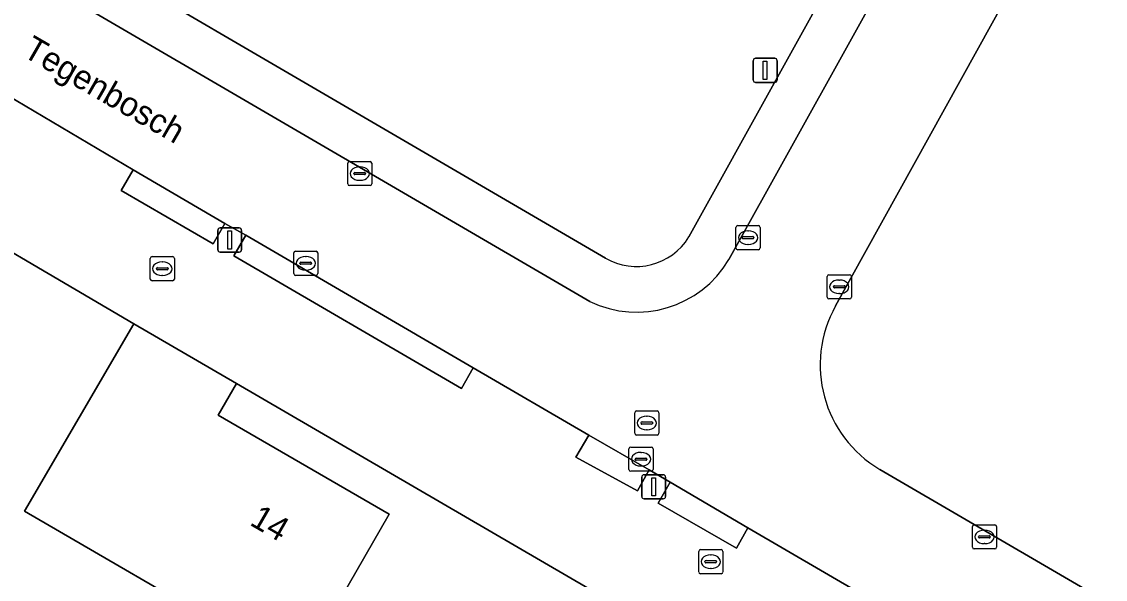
# Model space of a CAD drawing. Extents: x 156502 to 159075, y 384229 to 386100.
# Drawn here: x 157150.95 to 157195.85, y 385818.95 to 385842.02 of the extents above; entities that cross this region are included whole.
import ezdxf

# ---------------------------------------------------------------- set-up
doc = ezdxf.new("R2010")
doc.units = 0
for name, color, linetype in [('IMGEO_Brandkraan', 7, 'Continuous'), ('IMGEO_Erf', 7, 'Continuous'), ('IMGEO_Grasland_overig', 7, 'Continuous'), ('IMGEO_Groenvoorziening', 7, 'Continuous'), ('IMGEO_Haag', 7, 'Continuous'), ('IMGEO_Hek', 7, 'Continuous'), ('IMGEO_Kolk', 7, 'Continuous'), ('IMGEO_Lichtmast', 7, 'Continuous'), ('IMGEO_Openbare_ruimte_label', 7, 'Continuous'), ('IMGEO_Pand', 7, 'Continuous'), ('IMGEO_Pand_nummerreeks', 7, 'Continuous'), ('IMGEO_Parkeervlak_open', 7, 'Continuous'), ('IMGEO_Rijbaan_lokaal_open', 7, 'Continuous'), ('IMGEO_Rioolput', 7, 'Continuous'), ('IMGEO_Voetpad_open', 7, 'Continuous')]:
    doc.layers.add(name, color=color, linetype=linetype)

msp = doc.modelspace()

# ---------------------------------------------------------------- linework, layer by layer
at = {"layer": 'IMGEO_Brandkraan'}
for p, q in [((157156.28, 385831.377), (157156.28, 385832.229)), ((157156.355, 385832.303), (157157.207, 385832.303)), ((157156.768, 385832.083), (157156.793, 385832.083)), ((157157.281, 385832.229), (157157.281, 385831.377)), ((157156.539, 385831.797), (157156.539, 385831.809)), ((157156.977, 385831.76), (157156.579, 385831.76)), ((157156.582, 385831.846), (157156.98, 385831.846)), ((157156.791, 385831.523), (157156.766, 385831.523)), ((157157.023, 385831.809), (157157.023, 385831.797)), ((157157.207, 385831.303), (157156.355, 385831.303))]:
    msp.add_line(p, q, dxfattribs=at)
for points in [[(157156.28, 385831.377), (157156.28, 385832.229)], [(157156.355, 385832.303), (157157.207, 385832.303)], [(157157.281, 385832.229), (157157.281, 385831.377)], [(157157.207, 385831.303), (157156.355, 385831.303)]]:
    msp.add_lwpolyline(points, dxfattribs=at)
for centre, radius, start, end in [((157156.357, 385832.227), 0.0765, 91.552, 178.448), ((157156.357, 385832.227), 0.0765, 91.552, 178.448), ((157157.205, 385832.227), 0.0765, 1.552, 88.448), ((157157.205, 385832.227), 0.0765, 1.552, 88.448), ((157156.579, 385831.806), 0.0403, 85.8775, 175.7526), ((157156.576, 385831.796), 0.0366, 178.938, 274.7102), ((157156.98, 385831.803), 0.043, 264.8664, 352.4533), ((157156.984, 385831.808), 0.0386, 1.7309, 96.639), ((157156.357, 385831.379), 0.0765, 181.552, 268.448), ((157156.357, 385831.379), 0.0765, 181.552, 268.448), ((157157.205, 385831.379), 0.0765, 271.552, 358.448), ((157157.205, 385831.379), 0.0765, 271.552, 358.448)]:
    msp.add_arc(centre, radius, start, end, dxfattribs=at)
for centre, major_axis, ratio, start_param, end_param in [((157156.767, 385831.803), (-0.387, 0.002), 0.722429, 4.712389, 7.853982), ((157156.792, 385831.803), (-0.39, 0.002), 0.717154, 1.570796, 4.712389)]:
    msp.add_ellipse(centre, major_axis=major_axis, ratio=ratio, start_param=start_param, end_param=end_param, dxfattribs=at)
at = {"layer": 'IMGEO_Erf'}
for points in [[(157160.195, 385816.468), (157151.075, 385821.767), (157155.595, 385829.52), (157146.045, 385835.121)], [(157183.031, 385813.57), (157159.85, 385827.054), (157159.093, 385825.747), (157166.175, 385821.643), (157162.465, 385815.184)]]:
    msp.add_lwpolyline(points, dxfattribs=at)
at = {"layer": 'IMGEO_Grasland_overig'}
for points in [[(157198.923, 385855.959), (157184.675, 385830.26)], [(157186.511, 385823.495), (157214.196, 385807.371), (157215.153, 385806.818), (157210.12, 385798.131), (157215.692, 385794.809), (157216.71, 385794.202), (157246.925, 385776.791), (157272.043, 385820.045)]]:
    msp.add_lwpolyline(points, dxfattribs=at)
msp.add_arc((157189.041, 385827.813), 5.005, 150.7337, 239.6346, dxfattribs=at)
at = {"layer": 'IMGEO_Groenvoorziening'}
for points in [[(157120.919, 385863.835), (157175.135, 385832.241)], [(157178.593, 385833.119), (157193.488, 385859.938)]]:
    msp.add_lwpolyline(points, dxfattribs=at)
for points in [[(157159.377, 385833.674), (157155.57, 385835.897), (157155.076, 385835.039), (157158.886, 385832.827)], [(157160.239, 385833.196), (157159.74, 385832.335), (157169.178, 385826.84), (157169.662, 385827.706)], [(157174.449, 385824.915), (157173.918, 385823.999), (157176.468, 385822.604), (157176.957, 385823.481)], [(157177.826, 385822.969), (157177.317, 385822.102), (157180.564, 385820.235), (157181.039, 385821.079)]]:
    msp.add_lwpolyline(points, close=True, dxfattribs=at)
msp.add_arc((157176.416, 385834.444), 2.549, 239.8269, 328.6663, dxfattribs=at)
at = {"layer": 'IMGEO_Haag'}
for points in [[(157159.377, 385833.674), (157155.57, 385835.897), (157155.076, 385835.039), (157158.886, 385832.827)], [(157160.239, 385833.196), (157159.74, 385832.335), (157169.178, 385826.84), (157169.662, 385827.706)], [(157174.449, 385824.915), (157173.918, 385823.999), (157176.468, 385822.604), (157176.957, 385823.481)], [(157177.826, 385822.969), (157177.317, 385822.102), (157180.564, 385820.235), (157181.039, 385821.079)]]:
    msp.add_lwpolyline(points, close=True, dxfattribs=at)
at = {"layer": 'IMGEO_Hek'}
for points in [[(157155.595, 385829.52), (157146.045, 385835.121)], [(157183.031, 385813.57), (157159.85, 385827.054)]]:
    msp.add_lwpolyline(points, dxfattribs=at)
at = {"layer": 'IMGEO_Kolk'}
for p, q in [((157164.46, 385835.314), (157164.46, 385836.166)), ((157164.535, 385836.24), (157165.387, 385836.24)), ((157164.948, 385836.02), (157164.973, 385836.02)), ((157165.461, 385836.166), (157165.461, 385835.314)), ((157164.719, 385835.734), (157164.719, 385835.746)), ((157165.157, 385835.697), (157164.759, 385835.697)), ((157164.762, 385835.783), (157165.16, 385835.783)), ((157165.203, 385835.746), (157165.203, 385835.734)), ((157165.387, 385835.24), (157164.535, 385835.24)), ((157164.971, 385835.46), (157164.946, 385835.46)), ((157180.547, 385832.663), (157180.547, 385833.515)), ((157180.622, 385833.589), (157181.474, 385833.589)), ((157181.035, 385833.369), (157181.06, 385833.369)), ((157181.548, 385833.515), (157181.548, 385832.663)), ((157180.806, 385833.083), (157180.806, 385833.095)), ((157181.244, 385833.046), (157180.846, 385833.046)), ((157180.849, 385833.132), (157181.247, 385833.132)), ((157181.29, 385833.095), (157181.29, 385833.083)), ((157162.223, 385831.602), (157162.223, 385832.454)), ((157162.298, 385832.528), (157163.15, 385832.528)), ((157163.224, 385832.454), (157163.224, 385831.602)), ((157181.474, 385832.589), (157180.622, 385832.589)), ((157181.058, 385832.809), (157181.033, 385832.809)), ((157162.482, 385832.022), (157162.482, 385832.034)), ((157162.92, 385831.985), (157162.522, 385831.985)), ((157162.525, 385832.071), (157162.923, 385832.071)), ((157162.711, 385832.308), (157162.736, 385832.308)), ((157162.966, 385832.034), (157162.966, 385832.022)), ((157163.15, 385831.528), (157162.298, 385831.528)), ((157162.734, 385831.748), (157162.709, 385831.748)), ((157184.325, 385830.628), (157184.325, 385831.48)), ((157184.4, 385831.554), (157185.252, 385831.554)), ((157185.326, 385831.48), (157185.326, 385830.628)), ((157184.584, 385831.048), (157184.584, 385831.06)), ((157184.627, 385831.097), (157185.025, 385831.097)), ((157184.813, 385831.334), (157184.838, 385831.334)), ((157185.068, 385831.06), (157185.068, 385831.048)), ((157185.022, 385831.011), (157184.624, 385831.011)), ((157184.836, 385830.774), (157184.811, 385830.774)), ((157185.252, 385830.554), (157184.4, 385830.554)), ((157176.113, 385823.494), (157176.113, 385824.346)), ((157176.188, 385824.42), (157177.04, 385824.42)), ((157177.114, 385824.346), (157177.114, 385823.494)), ((157176.372, 385823.914), (157176.372, 385823.926)), ((157176.81, 385823.877), (157176.412, 385823.877)), ((157176.415, 385823.963), (157176.813, 385823.963)), ((157176.601, 385824.2), (157176.626, 385824.2)), ((157176.856, 385823.926), (157176.856, 385823.914)), ((157177.04, 385823.42), (157176.188, 385823.42)), ((157176.624, 385823.64), (157176.599, 385823.64)), ((157190.416, 385821.205), (157191.268, 385821.205)), ((157190.341, 385820.279), (157190.341, 385821.131)), ((157190.6, 385820.699), (157190.6, 385820.711)), ((157190.643, 385820.748), (157191.041, 385820.748)), ((157190.829, 385820.985), (157190.854, 385820.985)), ((157191.084, 385820.711), (157191.084, 385820.699)), ((157191.342, 385821.131), (157191.342, 385820.279)), ((157191.038, 385820.662), (157190.64, 385820.662)), ((157190.852, 385820.425), (157190.827, 385820.425)), ((157191.268, 385820.205), (157190.416, 385820.205))]:
    msp.add_line(p, q, dxfattribs=at)
for points in [[(157164.46, 385835.314), (157164.46, 385836.166)], [(157164.535, 385836.24), (157165.387, 385836.24)], [(157165.461, 385836.166), (157165.461, 385835.314)], [(157165.387, 385835.24), (157164.535, 385835.24)], [(157180.547, 385832.663), (157180.547, 385833.515)], [(157180.622, 385833.589), (157181.474, 385833.589)], [(157181.548, 385833.515), (157181.548, 385832.663)], [(157162.223, 385831.602), (157162.223, 385832.454)], [(157162.298, 385832.528), (157163.15, 385832.528)], [(157163.224, 385832.454), (157163.224, 385831.602)], [(157181.474, 385832.589), (157180.622, 385832.589)], [(157163.15, 385831.528), (157162.298, 385831.528)], [(157184.325, 385830.628), (157184.325, 385831.48)], [(157184.4, 385831.554), (157185.252, 385831.554)], [(157185.326, 385831.48), (157185.326, 385830.628)], [(157185.252, 385830.554), (157184.4, 385830.554)], [(157176.113, 385823.494), (157176.113, 385824.346)], [(157176.188, 385824.42), (157177.04, 385824.42)], [(157177.114, 385824.346), (157177.114, 385823.494)], [(157177.04, 385823.42), (157176.188, 385823.42)], [(157190.416, 385821.205), (157191.268, 385821.205)], [(157190.341, 385820.279), (157190.341, 385821.131)], [(157191.342, 385821.131), (157191.342, 385820.279)], [(157191.268, 385820.205), (157190.416, 385820.205)]]:
    msp.add_lwpolyline(points, dxfattribs=at)
for centre, radius, start, end in [((157164.537, 385836.164), 0.0765, 91.552, 178.448), ((157164.537, 385836.164), 0.0765, 91.552, 178.448), ((157165.385, 385836.164), 0.0765, 1.552, 88.448), ((157165.385, 385836.164), 0.0765, 1.552, 88.448), ((157164.759, 385835.743), 0.0403, 85.8775, 175.7526), ((157164.756, 385835.733), 0.0366, 178.938, 274.7102), ((157165.16, 385835.74), 0.043, 264.8664, 352.4533), ((157165.164, 385835.745), 0.0386, 1.7309, 96.639), ((157164.537, 385835.316), 0.0765, 181.552, 268.448), ((157164.537, 385835.316), 0.0765, 181.552, 268.448), ((157165.385, 385835.316), 0.0765, 271.552, 358.448), ((157165.385, 385835.316), 0.0765, 271.552, 358.448), ((157180.624, 385833.513), 0.0765, 91.552, 178.448), ((157180.624, 385833.513), 0.0765, 91.552, 178.448), ((157181.472, 385833.513), 0.0765, 1.552, 88.448), ((157181.472, 385833.513), 0.0765, 1.552, 88.448), ((157180.846, 385833.092), 0.0403, 85.8775, 175.7526), ((157180.843, 385833.082), 0.0366, 178.938, 274.7102), ((157181.247, 385833.089), 0.043, 264.8664, 352.4533), ((157181.251, 385833.094), 0.0386, 1.7309, 96.639), ((157162.3, 385832.452), 0.0765, 91.552, 178.448), ((157162.3, 385832.452), 0.0765, 91.552, 178.448), ((157163.148, 385832.452), 0.0765, 1.552, 88.448), ((157163.148, 385832.452), 0.0765, 1.552, 88.448), ((157180.624, 385832.665), 0.0765, 181.552, 268.448), ((157180.624, 385832.665), 0.0765, 181.552, 268.448), ((157181.472, 385832.665), 0.0765, 271.552, 358.448), ((157181.472, 385832.665), 0.0765, 271.552, 358.448), ((157162.522, 385832.031), 0.0403, 85.8775, 175.7526), ((157162.519, 385832.021), 0.0366, 178.938, 274.7102), ((157162.923, 385832.028), 0.043, 264.8664, 352.4533), ((157162.927, 385832.033), 0.0386, 1.7309, 96.639), ((157162.3, 385831.604), 0.0765, 181.552, 268.448), ((157162.3, 385831.604), 0.0765, 181.552, 268.448), ((157163.148, 385831.604), 0.0765, 271.552, 358.448), ((157163.148, 385831.604), 0.0765, 271.552, 358.448), ((157184.402, 385831.478), 0.0765, 91.552, 178.448), ((157184.402, 385831.478), 0.0765, 91.552, 178.448), ((157185.25, 385831.478), 0.0765, 1.552, 88.448), ((157185.25, 385831.478), 0.0765, 1.552, 88.448), ((157184.624, 385831.057), 0.0403, 85.8775, 175.7526), ((157184.621, 385831.047), 0.0366, 178.938, 274.7102), ((157185.025, 385831.054), 0.043, 264.8664, 352.4533), ((157185.029, 385831.059), 0.0386, 1.7309, 96.639), ((157184.402, 385830.63), 0.0765, 181.552, 268.448), ((157184.402, 385830.63), 0.0765, 181.552, 268.448), ((157185.25, 385830.63), 0.0765, 271.552, 358.448), ((157185.25, 385830.63), 0.0765, 271.552, 358.448), ((157176.19, 385824.344), 0.0765, 91.552, 178.448), ((157176.19, 385824.344), 0.0765, 91.552, 178.448), ((157177.038, 385824.344), 0.0765, 1.552, 88.448), ((157177.038, 385824.344), 0.0765, 1.552, 88.448), ((157176.412, 385823.923), 0.0403, 85.8775, 175.7526), ((157176.409, 385823.913), 0.0366, 178.938, 274.7102), ((157176.813, 385823.92), 0.043, 264.8664, 352.4533), ((157176.817, 385823.925), 0.0386, 1.7309, 96.639), ((157176.19, 385823.496), 0.0765, 181.552, 268.448), ((157176.19, 385823.496), 0.0765, 181.552, 268.448), ((157177.038, 385823.496), 0.0765, 271.552, 358.448), ((157177.038, 385823.496), 0.0765, 271.552, 358.448), ((157190.418, 385821.129), 0.0765, 91.552, 178.448), ((157190.418, 385821.129), 0.0765, 91.552, 178.448), ((157191.266, 385821.129), 0.0765, 1.552, 88.448), ((157191.266, 385821.129), 0.0765, 1.552, 88.448), ((157190.64, 385820.708), 0.0403, 85.8775, 175.7526), ((157190.637, 385820.698), 0.0366, 178.938, 274.7102), ((157191.041, 385820.705), 0.043, 264.8664, 352.4533), ((157191.045, 385820.71), 0.0386, 1.7309, 96.639), ((157190.418, 385820.281), 0.0765, 181.552, 268.448), ((157190.418, 385820.281), 0.0765, 181.552, 268.448), ((157191.266, 385820.281), 0.0765, 271.552, 358.448), ((157191.266, 385820.281), 0.0765, 271.552, 358.448)]:
    msp.add_arc(centre, radius, start, end, dxfattribs=at)
for centre, major_axis, ratio, start_param, end_param in [((157164.947, 385835.74), (-0.387, 0.002), 0.722429, 4.712389, 7.853982), ((157164.972, 385835.74), (-0.39, 0.002), 0.717154, 1.570796, 4.712389), ((157181.034, 385833.089), (-0.387, 0.002), 0.722429, 4.712389, 7.853982), ((157181.059, 385833.089), (-0.39, 0.002), 0.717154, 1.570796, 4.712389), ((157162.71, 385832.028), (-0.387, 0.002), 0.722429, 4.712389, 7.853982), ((157162.735, 385832.028), (-0.39, 0.002), 0.717154, 1.570796, 4.712389), ((157184.812, 385831.054), (-0.387, 0.002), 0.722429, 4.712389, 7.853982), ((157184.837, 385831.054), (-0.39, 0.002), 0.717154, 1.570796, 4.712389), ((157176.6, 385823.92), (-0.387, 0.002), 0.722429, 4.712389, 7.853982), ((157176.625, 385823.92), (-0.39, 0.002), 0.717154, 1.570796, 4.712389), ((157190.828, 385820.705), (-0.387, 0.002), 0.722429, 4.712389, 7.853982), ((157190.853, 385820.705), (-0.39, 0.002), 0.717154, 1.570796, 4.712389)]:
    msp.add_ellipse(centre, major_axis=major_axis, ratio=ratio, start_param=start_param, end_param=end_param, dxfattribs=at)
at = {"layer": 'IMGEO_Lichtmast'}
for p, q in [((157181.36, 385840.512), (157182.15, 385840.512)), ((157182.15, 385840.512), (157181.36, 385840.512)), ((157181.26, 385839.612), (157181.26, 385840.412)), ((157181.26, 385840.412), (157181.26, 385839.612)), ((157182.25, 385840.412), (157182.25, 385839.612)), ((157182.25, 385839.612), (157182.25, 385840.412)), ((157182.15, 385839.512), (157181.36, 385839.512)), ((157181.36, 385839.512), (157182.15, 385839.512)), ((157159.075, 385832.59), (157159.075, 385833.39)), ((157159.075, 385833.39), (157159.075, 385832.59)), ((157159.175, 385833.49), (157159.965, 385833.49)), ((157159.965, 385833.49), (157159.175, 385833.49)), ((157160.065, 385833.39), (157160.065, 385832.59)), ((157160.065, 385832.59), (157160.065, 385833.39)), ((157159.965, 385832.49), (157159.175, 385832.49)), ((157159.175, 385832.49), (157159.965, 385832.49)), ((157176.642, 385822.379), (157176.642, 385823.179)), ((157176.642, 385823.179), (157176.642, 385822.379)), ((157176.742, 385823.279), (157177.532, 385823.279)), ((157177.532, 385823.279), (157176.742, 385823.279)), ((157177.632, 385823.179), (157177.632, 385822.379)), ((157177.632, 385822.379), (157177.632, 385823.179)), ((157177.532, 385822.279), (157176.742, 385822.279)), ((157176.742, 385822.279), (157177.532, 385822.279))]:
    msp.add_line(p, q, dxfattribs=at)
for points in [[(157181.68, 385840.387), (157181.83, 385840.387), (157181.83, 385839.637), (157181.68, 385839.637), (157181.68, 385840.387)], [(157159.495, 385833.365), (157159.645, 385833.365), (157159.645, 385832.615), (157159.495, 385832.615), (157159.495, 385833.365)], [(157177.062, 385823.154), (157177.212, 385823.154), (157177.212, 385822.404), (157177.062, 385822.404), (157177.062, 385823.154)]]:
    msp.add_lwpolyline(points, dxfattribs=at)
for centre, start, end in [((157181.36, 385840.412), 90, 180), ((157181.36, 385840.412), 90, 180), ((157182.15, 385840.412), 0, 90), ((157182.15, 385840.412), 360, 90), ((157181.36, 385839.612), 180, 270), ((157181.36, 385839.612), 180, 270), ((157182.15, 385839.612), 270, 0), ((157182.15, 385839.612), 270, 0), ((157159.175, 385833.39), 90, 180), ((157159.175, 385833.39), 90, 180), ((157159.965, 385833.39), 0, 90), ((157159.965, 385833.39), 360, 90), ((157159.175, 385832.59), 180, 270), ((157159.175, 385832.59), 180, 270), ((157159.965, 385832.59), 270, 0), ((157159.965, 385832.59), 270, 0), ((157176.742, 385823.179), 90, 180), ((157176.742, 385823.179), 90, 180), ((157177.532, 385823.179), 0, 90), ((157177.532, 385823.179), 360, 90), ((157176.742, 385822.379), 180, 270), ((157176.742, 385822.379), 180, 270), ((157177.532, 385822.379), 270, 0), ((157177.532, 385822.379), 270, 0)]:
    msp.add_arc(centre, 0.1, start, end, dxfattribs=at)
at = {"layer": 'IMGEO_Pand'}
msp.add_lwpolyline([(157155.595, 385829.52), (157151.075, 385821.767), (157160.195, 385816.468), (157159.704, 385815.599), (157159.324, 385815.821), (157155.962, 385810.061), (157163.329, 385805.74), (157166.702, 385811.491), (157161.733, 385814.451), (157162.231, 385815.319), (157162.465, 385815.184), (157166.175, 385821.643), (157159.093, 385825.747), (157159.85, 385827.054)], close=True, dxfattribs=at)
at = {"layer": 'IMGEO_Parkeervlak_open'}
for points in [[(157175.135, 385832.241), (157120.919, 385863.835)], [(157119.853, 385862.285), (157174.491, 385830.448)], [(157193.488, 385859.938), (157178.593, 385833.119)], [(157180.25, 385832.18), (157195.227, 385859.097)]]:
    msp.add_lwpolyline(points, dxfattribs=at)
for centre, radius, start, end in [((157176.416, 385834.444), 2.549, 239.8269, 328.6663), ((157176.428, 385834.448), 4.444, 244.161, 329.3159)]:
    msp.add_arc(centre, radius, start, end, dxfattribs=at)
at = {"layer": 'IMGEO_Rijbaan_lokaal_open'}
for points in [[(157112.461, 385867.56), (157109.666, 385862.678), (157112.261, 385861.167), (157116.486, 385858.694), (157117.345, 385858.202), (157126.778, 385852.73), (157133.897, 385848.562), (157138.584, 385845.831), (157139.408, 385845.347), (157148.842, 385839.867), (157155.57, 385835.897), (157159.377, 385833.674), (157160.239, 385833.196), (157169.662, 385827.706), (157174.449, 385824.915), (157176.957, 385823.481), (157177.826, 385822.969), (157181.039, 385821.079), (157185.809, 385818.305)], [(157174.491, 385830.448), (157119.853, 385862.285)], [(157195.227, 385859.097), (157180.25, 385832.18)], [(157184.675, 385830.26), (157198.923, 385855.959)], [(157214.196, 385807.371), (157186.511, 385823.495)]]:
    msp.add_lwpolyline(points, dxfattribs=at)
for centre, radius, start, end in [((157176.428, 385834.448), 4.444, 244.161, 329.3159), ((157189.041, 385827.813), 5.005, 150.7337, 239.6346)]:
    msp.add_arc(centre, radius, start, end, dxfattribs=at)
at = {"layer": 'IMGEO_Rioolput'}
for p, q in [((157176.353, 385824.991), (157176.353, 385825.843)), ((157176.428, 385825.917), (157177.28, 385825.917)), ((157176.841, 385825.697), (157176.866, 385825.697)), ((157177.354, 385825.843), (157177.354, 385824.991)), ((157176.612, 385825.411), (157176.612, 385825.423)), ((157177.05, 385825.374), (157176.652, 385825.374)), ((157176.655, 385825.46), (157177.053, 385825.46)), ((157177.096, 385825.423), (157177.096, 385825.411)), ((157177.28, 385824.917), (157176.428, 385824.917)), ((157176.864, 385825.137), (157176.839, 385825.137)), ((157179.003, 385819.252), (157179.003, 385820.104)), ((157179.078, 385820.178), (157179.93, 385820.178)), ((157179.491, 385819.958), (157179.516, 385819.958)), ((157180.004, 385820.104), (157180.004, 385819.252)), ((157179.262, 385819.672), (157179.262, 385819.684)), ((157179.7, 385819.635), (157179.302, 385819.635)), ((157179.305, 385819.721), (157179.703, 385819.721)), ((157179.514, 385819.398), (157179.489, 385819.398)), ((157179.746, 385819.684), (157179.746, 385819.672)), ((157179.93, 385819.178), (157179.078, 385819.178))]:
    msp.add_line(p, q, dxfattribs=at)
for points in [[(157176.353, 385824.991), (157176.353, 385825.843)], [(157176.428, 385825.917), (157177.28, 385825.917)], [(157177.354, 385825.843), (157177.354, 385824.991)], [(157177.28, 385824.917), (157176.428, 385824.917)], [(157179.003, 385819.252), (157179.003, 385820.104)], [(157179.078, 385820.178), (157179.93, 385820.178)], [(157180.004, 385820.104), (157180.004, 385819.252)], [(157179.93, 385819.178), (157179.078, 385819.178)]]:
    msp.add_lwpolyline(points, dxfattribs=at)
for centre, radius, start, end in [((157176.43, 385825.841), 0.0765, 91.552, 178.448), ((157176.43, 385825.841), 0.0765, 91.552, 178.448), ((157177.278, 385825.841), 0.0765, 1.552, 88.448), ((157177.278, 385825.841), 0.0765, 1.552, 88.448), ((157176.652, 385825.42), 0.0403, 85.8775, 175.7526), ((157176.649, 385825.41), 0.0366, 178.938, 274.7102), ((157177.053, 385825.417), 0.043, 264.8664, 352.4533), ((157177.057, 385825.422), 0.0386, 1.7309, 96.639), ((157176.43, 385824.993), 0.0765, 181.552, 268.448), ((157176.43, 385824.993), 0.0765, 181.552, 268.448), ((157177.278, 385824.993), 0.0765, 271.552, 358.448), ((157177.278, 385824.993), 0.0765, 271.552, 358.448), ((157179.08, 385820.102), 0.0765, 91.552, 178.448), ((157179.08, 385820.102), 0.0765, 91.552, 178.448), ((157179.928, 385820.102), 0.0765, 1.552, 88.448), ((157179.928, 385820.102), 0.0765, 1.552, 88.448), ((157179.302, 385819.681), 0.0403, 85.8775, 175.7526), ((157179.299, 385819.671), 0.0366, 178.938, 274.7102), ((157179.703, 385819.678), 0.043, 264.8664, 352.4533), ((157179.707, 385819.683), 0.0386, 1.7309, 96.639), ((157179.08, 385819.254), 0.0765, 181.552, 268.448), ((157179.08, 385819.254), 0.0765, 181.552, 268.448), ((157179.928, 385819.254), 0.0765, 271.552, 358.448), ((157179.928, 385819.254), 0.0765, 271.552, 358.448)]:
    msp.add_arc(centre, radius, start, end, dxfattribs=at)
for centre, major_axis, ratio, start_param, end_param in [((157176.84, 385825.417), (-0.387, 0.002), 0.722429, 4.712389, 7.853982), ((157176.865, 385825.417), (-0.39, 0.002), 0.717154, 1.570796, 4.712389), ((157179.49, 385819.678), (-0.387, 0.002), 0.722429, 4.712389, 7.853982), ((157179.515, 385819.678), (-0.39, 0.002), 0.717154, 1.570796, 4.712389)]:
    msp.add_ellipse(centre, major_axis=major_axis, ratio=ratio, start_param=start_param, end_param=end_param, dxfattribs=at)
at = {"layer": 'IMGEO_Voetpad_open'}
for points in [[(157116.16, 385883.109), (157114.16, 385884.269), (157111.651, 385879.994), (157106.141, 385870.607), (157105.837, 385870.09), (157105.698, 385869.85), (157102.227, 385863.854), (157101.95, 385864.014), (157100.545, 385861.579), (157100.836, 385861.41), (157106.562, 385858.084), (157112.648, 385854.542), (157123.992, 385847.954), (157134.715, 385841.68), (157146.045, 385835.121), (157155.595, 385829.52), (157159.85, 385827.054), (157183.031, 385813.57)], [(157177.317, 385822.102), (157177.826, 385822.969), (157176.957, 385823.481), (157176.468, 385822.604), (157173.918, 385823.999), (157174.449, 385824.915), (157169.662, 385827.706), (157169.178, 385826.84), (157159.74, 385832.335), (157160.239, 385833.196), (157159.377, 385833.674), (157158.886, 385832.827), (157155.076, 385835.039), (157155.57, 385835.897), (157148.842, 385839.867)], [(157185.809, 385818.305), (157181.039, 385821.079), (157180.564, 385820.235), (157177.317, 385822.102)]]:
    msp.add_lwpolyline(points, dxfattribs=at)

# ---------------------------------------------------------------- texts
at = {"layer": 'IMGEO_Openbare_ruimte_label'}
msp.add_text('Tegenbosch', height=1, rotation=330.0489, dxfattribs=at).set_placement((157150.949, 385840.623))
at = {"layer": 'IMGEO_Pand_nummerreeks'}
msp.add_text('14', height=1, rotation=329.9055, dxfattribs=at).set_placement((157160.356, 385821.224))

doc.saveas('drawing.dxf')
